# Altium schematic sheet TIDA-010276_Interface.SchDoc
size 431 x 279 mm; Date: Not shown in title block; ApprovedBy: Not shown in title block; CheckedBy: Not shown in title block; Author: Not shown in title block; CompanyName: Not shown in title block; DrawnBy: Jenson Fang; Engineer: Jenson Fang; Organization: Not shown in title block; Address1: Not shown in title block; Address2: Not shown in title block; Address3: Not shown in title block; Address4: Not shown in title block; DocumentNumber: 1; Revision: Use project parameter SCH_Rev; SheetNumber: 5; SheetTotal: 6; PageSetup: Record=PageOptions¦CenterHorizontal=True¦CenterVertical=True¦PrintScale=1.00¦XCorrection=1.00¦YCorrection=1.00¦PrintKind=0¦BorderSize=5000000¦LeftOffset=0¦BottomOffset=0¦Orientation=2¦PaperLength=1000¦PaperWidth=1000¦Scale=100¦PaperSource=15¦PrintQuality=600¦MediaType=1¦DitherType=10¦PaperKind=Letter¦PrintScaleMode=1
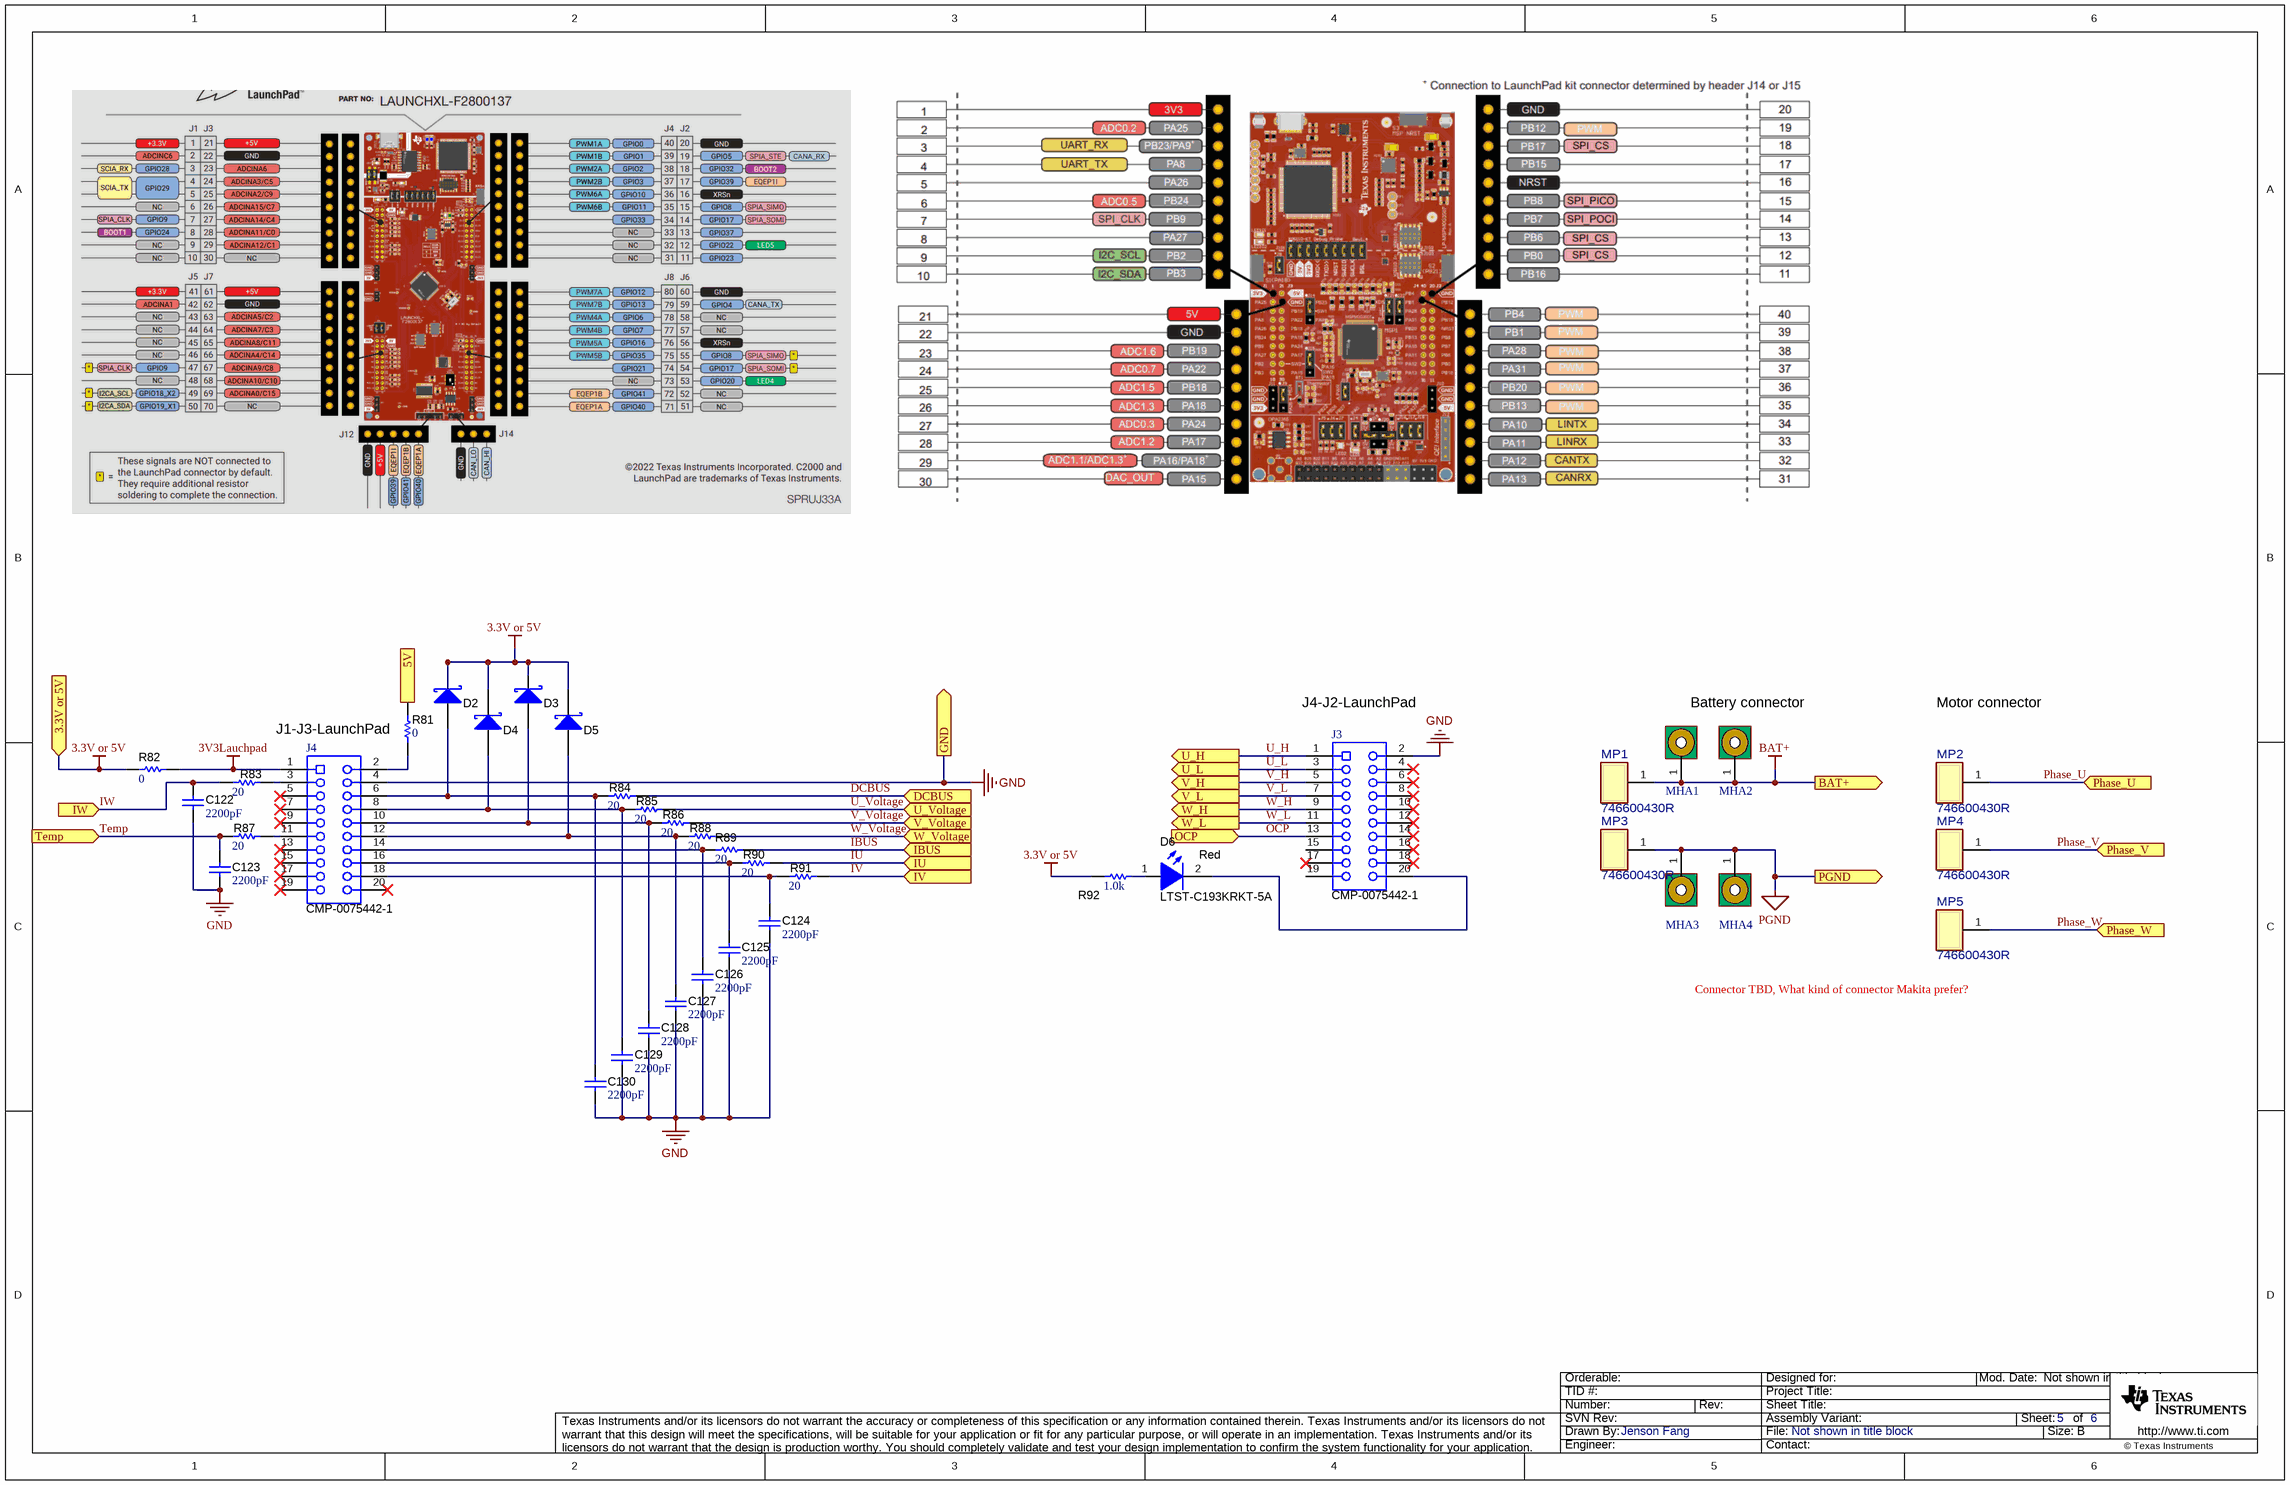
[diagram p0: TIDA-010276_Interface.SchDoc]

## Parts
C122  ValueDisplayed: 2200pF  [0603]  (hidden comment: CMP-0006827-4)
C123  ValueDisplayed: 2200pF  [0603]  (hidden comment: CMP-0006827-4)
C124  ValueDisplayed: 2200pF  [0603]  (hidden comment: CMP-0006827-4)
C125  ValueDisplayed: 2200pF  [0603]  (hidden comment: CMP-0006827-4)
C126  ValueDisplayed: 2200pF  [0603]  (hidden comment: CMP-0006827-4)
C127  ValueDisplayed: 2200pF  [0603]  (hidden comment: CMP-0006827-4)
C128  ValueDisplayed: 2200pF  [0603]  (hidden comment: CMP-0006827-4)
C129  ValueDisplayed: 2200pF  [0603]  (hidden comment: CMP-0006827-4)
C130  ValueDisplayed: 2200pF  [0603]  (hidden comment: CMP-0006827-4)
D2  CMP-0028644-3  [SOD-523]  (value not drawn)
D3  CMP-0028644-3  [SOD-523]  (value not drawn)
D4  CMP-0028644-3  [SOD-523]  (value not drawn)
D5  CMP-0028644-3  [SOD-523]  (value not drawn)
D6  LTST-C193KRKT-5A  value Red  [LTST-C193_Red]
J3  CMP-0075442-1  [CONN_SSW-110-23-F-D]
J4  CMP-0075442-1  [CONN_SSW-110-23-F-D]
MHA1  MTG_Pads_M4  [MTGP_M4_Washer]  (value not drawn)  (no BOM)
MHA2  MTG_Pads_M4  [MTGP_M4_Washer]  (value not drawn)  (no BOM)
MHA3  MTG_Pads_M4  [MTGP_M4_Washer]  (value not drawn)  (no BOM)
MHA4  MTG_Pads_M4  [MTGP_M4_Washer]  (value not drawn)  (no BOM)
MP1  746600430R  [FP-746600430R_SMT_SCREW_TERMINAL_7MM0-MFG]
MP2  746600430R  [FP-746600430R_SMT_SCREW_TERMINAL_7MM0-MFG]
MP3  746600430R  [FP-746600430R_SMT_SCREW_TERMINAL_7MM0-MFG]
MP4  746600430R  [FP-746600430R_SMT_SCREW_TERMINAL_7MM0-MFG]
MP5  746600430R  [FP-746600430R_SMT_SCREW_TERMINAL_7MM0-MFG]
R81  ValueDisplayed: 0  [0603]  (hidden comment: PMR03EZPJ000)
R82  ValueDisplayed: 0  [0603]  (hidden comment: PMR03EZPJ000)
R83  ValueDisplayed: 20  [0402]  (hidden comment: CMP-0026876-3)
R84  ValueDisplayed: 20  [0402]  (hidden comment: CMP-0026876-3)
R85  ValueDisplayed: 20  [0402]  (hidden comment: CMP-0026876-3)
R86  ValueDisplayed: 20  [0402]  (hidden comment: CMP-0026876-3)
R87  ValueDisplayed: 20  [0402]  (hidden comment: CMP-0026876-3)
R88  ValueDisplayed: 20  [0402]  (hidden comment: CMP-0026876-3)
R89  ValueDisplayed: 20  [0402]  (hidden comment: CMP-0026876-3)
R90  ValueDisplayed: 20  [0402]  (hidden comment: CMP-0026876-3)
R91  ValueDisplayed: 20  [0402]  (hidden comment: CMP-0026876-3)
R92  ValueDisplayed: 1.0k  [0603]  (hidden comment: RC0603JR-071KL)

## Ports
3.3V or 5V (in), 5V (in), BAT+ (out), DCBUS (in), GND (out), IBUS (in), IU (in), IV (in), IW (in), OCP (in), PGND (out), Phase_U (in), Phase_V (in), Phase_W (in), Temp (in), U_H (out), U_L (out), U_Voltage (in), V_H (out), V_L (out), V_Voltage (in), W_H (out), W_L (out), W_Voltage (in)

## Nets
3.3V or 5V: D2.1(K) D3.1(K) D4.1(K) D5.1(K) R82.2 R92.1 ; port 3.3V or 5V
3V3Lauchpad: J4.1 R82.1
BAT+: MHA1.1 MHA2.1 MP1.1 ; port BAT+
GND: C122.2 C123.2 C124.2 C125.2 C126.2 C127.2 C128.2 C129.2 C130.2 J3.2 J4.4 ; port GND
PGND: MHA3.1 MHA4.1 MP3.1 ; port PGND
5V: R81.1 ; port 5V
DCBUS: R84.1 ; port DCBUS
IBUS: R89.1 ; port IBUS
IU: R90.1 ; port IU
IV: R91.1 ; port IV
IW: C122.1 R83.2 ; port IW
OCP: J3.13 ; port OCP
Phase_U: MP2.1 ; port Phase_U
Phase_V: MP4.1 ; port Phase_V
Phase_W: MP5.1 ; port Phase_W
Temp: C123.1 R87.2 ; port Temp
U_H: J3.1 ; port U_H
U_L: J3.3 ; port U_L
U_Voltage: R85.1 ; port U_Voltage
V_H: J3.5 ; port V_H
V_L: J3.7 ; port V_L
V_Voltage: R86.1 ; port V_Voltage
W_H: J3.9 ; port W_H
W_L: J3.11 ; port W_L
W_Voltage: R88.1 ; port W_Voltage
NetC124_1: C124.1 J4.18 R91.2
NetC125_1: C125.1 J4.16 R90.2
NetC126_1: C126.1 J4.14 R89.2
NetC127_1: C127.1 D5.2(A) J4.12 R88.2
NetC128_1: C128.1 D3.2(A) J4.10 R86.2
NetC129_1: C129.1 D4.2(A) J4.8 R85.2
NetC130_1: C130.1 D2.2(A) J4.6 R84.2
NetD6_1: D6.1(A) R92.2
NetD6_2: D6.2(K) J3.20
NetJ4_2: J4.2 R81.2
NetJ4_3: J4.3 R83.1
NetJ4_11: J4.11 R87.1

Not connected (* = marked no-connect by the designer): J3 4* 6* 8* 10* 12* 14* 15 16* 17* 18* 19; J4 5* 7* 9* 13* 15* 17* 19* 20*

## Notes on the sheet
- (near J3) J4-J2-LaunchPad
- Battery connector
- Motor connector
- J1-J3-LaunchPad
- Connector TBD, What kind of connector Makita prefer?

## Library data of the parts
C122-C130 = CMP-0006827-4: CAP, CERM, 2200 pF, 16 V, +/- 10%, X7R, 0603; PartNumber: 885012206036; Manufacturer: Wurth Elektronik; Polarized: N; Value: 2200pF; U/M: EA; Cap_F: 2.2nF; Value1: Unknown; VDC_V: 16V; TaMin_C: -55°C; TaMax_C: 125°C; AEC Category: Q200; SizeArea_mm2: 1.28; SizeAreaWB_mm2: 4.68; SizeX_mm: 1.6; SizeY_mm: 0.8; SizeZ_mm: 1
D2-D5 = CMP-0028644-3: Diode, Schottky, 70 V, 0.07 A, SOD-523; PartNumber: 1PS79SB70,115; Manufacturer: Nexperia; Vf_V: 410mV; Value: 70V; Value1: 0.07A; Value2: 0.41V; Io_A: 70mA; TJmax_C: 150°C; SizeAreaWB_mm2: 5.13; SizeArea_mm2: 1.53; SizeX_mm: 1.7; SizeY_mm: 0.9; SizeZ_mm: 0.65; AEC Category: Q101; Green_Lifecycle: Not Set; Green_REACh: Incomplete
D6 = CMP-0079922-3: LED, Red, SMD; Manufacturer: Lite-On; SizeX_mm: 1.6; Value2: 2V; SizeY_mm: 0.8; Green_REACh: Incomplete; SizeAreaWB_mm2: 4.68; Green_Lifecycle: Not Set; Value1: W; Io_A: 5mA; Type: AlInGaP; SizeZ_mm: 0.45; Tjmax_C: 85°C; SizeArea_mm2: 1.28
J3 J4 = CMP-0075442-1: Connector, Receptacle, 100mil, 10x2, Gold plated, TH; PartNumber: SSW-110-23-F-D; Manufacturer: Samtec; CompType: Socket Strip; Green_Lifecycle: Active; Green_REACh: Passed; CT: True; CNHeader: False
MHA1-MHA4 = CMP-00001-2: PCB Mounting Hole for M4; Manufacturer: Any; Key: Mounting Hole (Metric) with Pads for M4
MP1-MP5 = CMP-0094777-1: Pin Screw Terminal, Power Tap M4 Surface Mount; Manufacturer: Wurth Electronics; AEC Qualified: No; SizeZ_mm: 4.1mm; Is Female: yes
R81 R82 = CMP-0086358-1: RES, 0, 0%, 0.25 W, AEC-Q200 Grade 0, 0603; Manufacturer: Rohm; Power_W: 250mW; SizeZ_mm: 1; SizeArea_mm2: 1.28; Value2: 0.25W; SizeAreaWB_mm2: 4.68; Value_Code: 0000; Value: 0; AEC Qualified: Y; AEC Category: Q200; SizeX_mm: 1.6; SizeY_mm: 0.8
R83-R91 = CMP-0026876-3: RES, 20, 5%, 0.063 W, AEC-Q200 Grade 0, 0402; PartNumber: CRCW040220R0JNED; Manufacturer: Vishay-Dale; Value: 20; Value_Code: 20R0; Power_W: 63mW; Value2: 0.063W; VDC_V: 50V; TempCo: 200 ppm/C; EIA_Code: E24; AEC Category: Q200; AEC Qualified: Y; AEC Grade: 0; SizeArea_mm2: 0.5; SizeX_mm: 1; SizeZ_mm: 0.6
R92 = CMP-0025899-5: RES, 1.0 k, 5%, 0.1 W, 0603; Manufacturer: Yageo; Power_W: 100mW; TempCo: 100 ppm/C; Value_Code: 1k00; Value: 1.0k; EIA_Code: E24; Res_ohm: 1k; SizeX_mm: 1.6; SizeY_mm: 0.8; SizeZ_mm: 1; Value2: 0.1W; SizeArea_mm2: 1.28; AEC Qualified: N; VDC_V: 75V; AEC Category: Q200; SizeAreaWB_mm2: 4.68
